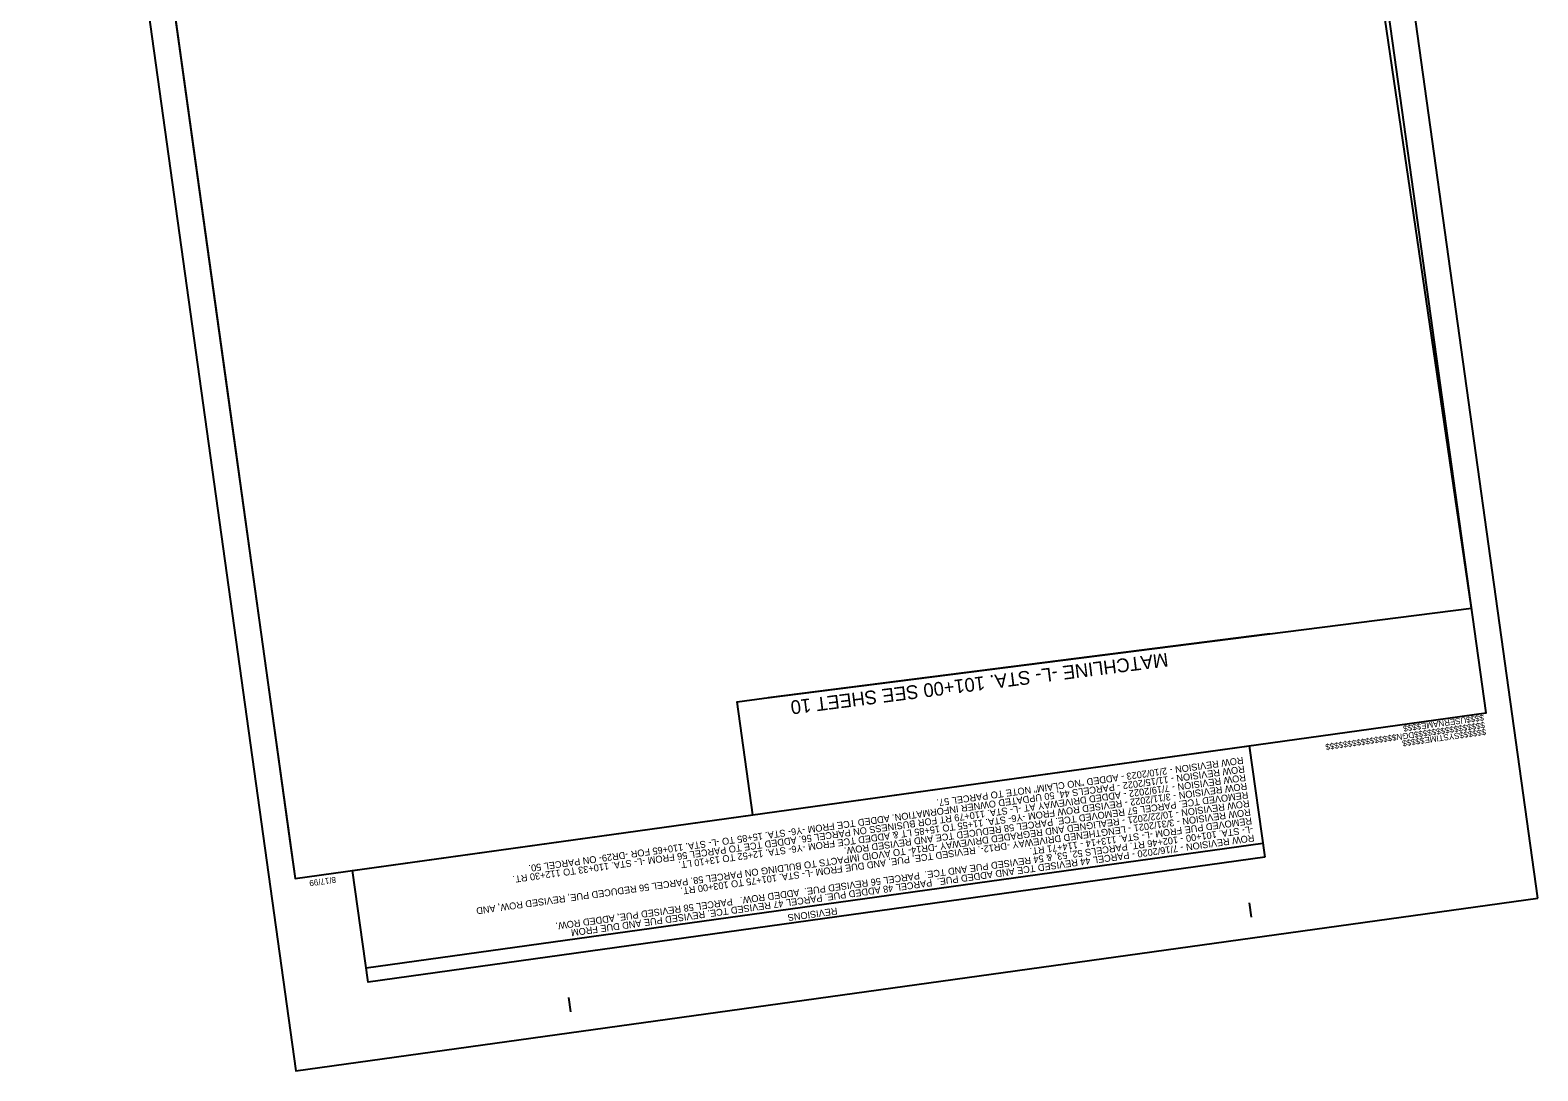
# Model space of a CAD drawing. Extents: x 477151 to 478666, y 496366 to 498184.
# Drawn here: x 477350 to 478666, y 496366 to 497275 of the extents above; entities that cross this region are included whole.
import ezdxf

# ---------------------------------------------------------------- set-up
doc = ezdxf.new("R2010")
doc.units = 0
for name, color, linetype in [('Matchline', 7, 'Continuous'), ('Matchline Text', 7, 'Continuous'), ('Sheet Block Revision CELL', 7, 'Continuous'), ('Sheet Clip Boundary CELL', 7, 'Continuous'), ('Sheet Plan CELL', 7, 'Continuous'), ('Sheet Plot Border Outside CELL', 7, 'Continuous')]:
    doc.layers.add(name, color=color, linetype=linetype)

msp = doc.modelspace()

# ---------------------------------------------------------------- linework, layer by layer
at = {"layer": 'Matchline'}
msp.add_line((478432.2, 496747.7), (477994, 496691.8), dxfattribs=at)
at = {"layer": 'Sheet Block Revision CELL'}
msp.add_line((478426.1, 496564.5), (477643, 496455.5), dxfattribs=at)
msp.add_lwpolyline([(478427.8, 496552.5), (477644.7, 496443.5), (477631.1, 496540.9), (478414.2, 496649.8)], close=True, dxfattribs=at)
at = {"layer": 'Sheet Clip Boundary CELL'}
msp.add_lwpolyline([(477521.6, 496961.1), (477576.8, 496564.4), (477581, 496533.9), (477980.8, 496589.5), (477967.1, 496688.3), (477990.6, 496691.4), (478608.2, 496770.2), (478458.7, 497790.4), (478383.4, 497784.9), (478355.7, 497984), (478358.5, 497984.3), (478349.1, 498051.5), (477730.1, 497965.3), (477560.3, 497941.7), (477573.7, 497845.4), (477401.8, 497821.4)], close=True, dxfattribs=at)
at = {"layer": 'Sheet Plan CELL'}
for p, q in [((478621, 496678.6), (478621, 496678.6)), ((477581, 496533.9), (477581, 496533.9)), ((478416.1, 496500.2), (478414.4, 496512.6)), ((477821.9, 496417.5), (477820.1, 496429.9))]:
    msp.add_line(p, q, dxfattribs=at)
msp.add_lwpolyline([(477374.2, 498019.6), (477581, 496533.9), (478621, 496678.6), (478414.2, 498164.3)], close=True, dxfattribs=at)
at = {"layer": 'Sheet Plot Border Outside CELL'}
msp.add_lwpolyline([(478666.2, 496516.8), (478434.2, 498184.2), (477349.6, 498033.3), (477581.7, 496365.9)], close=True, dxfattribs=at)

# ---------------------------------------------------------------- texts
at = {"layer": 'Matchline Text'}
msp.add_text('MATCHLINE -L- STA. 101+00 SEE SHEET 10', height=12, rotation=187.2759, dxfattribs=at).set_placement((478342.6, 496731.2))
at = {"layer": 'Sheet Block Revision CELL'}
for s, rotation, p in [('ROW REVISION - 2/10/2023 - ADDED "NO CLAIM" NOTE TO PARCEL 57. ', 187.9236, (478408.7, 496640.2)), ('ROW REVISION - 7/19/2022 - ADDED DRIVEWAY AT -L- STA. 110+79 RT FOR BUSINESS ON PARCEL 56. ADDED TCE TO PARCEL 56 FROM -L- STA. 110+33 TO 112+30 RT. ', 187.9236, (478410.8, 496625.1)), ('ROW REVISION - 11/15/2022 - PARCELS 44, 50 UPDATED OWNER INFORMATION. ADDED TCE FROM -Y6- STA. 15+85 TO -L- STA. 110+65 FOR -DR29- ON PARCEL 50. ', 187.9236, (478409.8, 496632.6)), ('ROW REVISION - 3/11/2022 - REVISED ROW FROM -Y6- STA. 11+55 TO 15+85 LT & ADDED TCE FROM -Y6- STA. 12+52 TO 13+10 LT. ', 187.9236, (478411.9, 496617.6)), ('REMOVED TCE. PARCEL 57 REMOVED TCE. PARCEL 58 REDUCED TCE AND REVISED ROW.  ', 187.9236, (478412.9, 496610)), ('ROW REVISION - 10/22/2021 - REALIGNED AND REGRADED DRIVEWAY -DR14- TO AVOID IMPACTS TO BULDING ON PARCEL 58. PARCEL 56 REDUCED PUE, REVISED ROW, AND ', 187.9236, (478414, 496602.5)), ('ROW REVISION - 3/31/2021 - LENGTHENED DRIVEWAY -DR12-. REVISED TCE, PUE, AND DUE FROM -L- STA. 101+75 TO 103+00 RT.', 187.9236, (478415, 496595)), ('REMOVED PUE FROM -L- STA. 113+14 - 114+71 RT.', 187.9236, (478416.1, 496587.4)), ('-L- STA. 101+00 - 102+46 RT. PARCELS 52, 53, & 54 REVISED PUE AND TCE.  PARCEL 56 REVISED PUE.  ADDED ROW.   PARCEL 58 REVISED PUE, ADDED ROW.', 187.9236, (478417.1, 496579.9)), ('ROW REVISION - 7/16/2020 - PARCEL 44 REVISED TCE AND ADDED PUE.  PARCEL 48 ADDED PUE. PARCEL 47 REVISED TCE. REVISED PUE AND DUE FROM', 187.9236, (478418.2, 496572.4)), ('REVISIONS', 187.9227, (478054.1, 496508.6))]:
    msp.add_text(s, height=6, rotation=rotation, dxfattribs=at).set_placement(p)
at = {"layer": 'Sheet Plan CELL'}
for s, p in [('$$$$USERNAME$$$$', (478618.8, 496677.2)), ('$$$$$$$$$$$$$$$$DGN$$$$$$$$$$$$$$$$', (478619.7, 496670.7)), ('$$$$$$SYSTIME$$$$$', (478620.6, 496664.7)), ('8/17/99', (477616.3, 496535.5))]:
    msp.add_text(s, height=5.25, rotation=187.9227, dxfattribs=at).set_placement(p)

doc.saveas('drawing.dxf')
